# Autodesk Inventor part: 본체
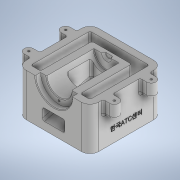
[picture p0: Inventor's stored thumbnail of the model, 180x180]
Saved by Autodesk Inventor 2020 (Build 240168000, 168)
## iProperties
Created: 2022-03
Part Number: 본체
Material: 일반
Document SubType Name: Modeling
Designer: Administrator
Density: 1 g/cm^3
Appearance: 기본값
Mass: 379.403 g
Surface Area: 844.892 cm^2
Volume: 379.403 cm^3
Author: Administrator
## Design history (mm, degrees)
sketch "스케치1"
  geometry: L1 (-55, -55)-(55, -55); L2 (55, -55)-(55, 55); L3 (55, 55)-(-55, 55); L4 (-55, 55)-(-55, -55); L5 (-55, -55)-(55, 55); L6 (55, -55)-(-55, 55); 1 further point
  constraints: 12 end point, 2 midpoint, 2 parallel, 1 horizontal, 1 perpendicular
  dimensions: "d0" = 110 distance of L2.end L3.end; "d1" = 110 distance of L3.end L1.start
extrude "돌출1" new body sketch "스케치1" distance "d2" = 65; taper "d3" = 0 deg
sketch "스케치3"
  geometry: L1 (-45, 45)-(45, 45); L2 (-45, 45)-(-45, -45); L3 (-45, -45)-(-30, -45); L4 (-30, -45)-(-30, 33); L5 (-30, 33)-(30, 33); L6 (30, 33)-(30, -45); L7 (45, 45)-(45, -45); L8 (45, -45)-(30, -45); L9 (-55, 55)-(-55, -55) reference; L10 (55, -55)-(55, 55) reference; L11 (55, 55)-(-55, 55) reference; L12 (-55, -55)-(55, -55) reference; 1 further point
  constraints: 16 end point, 5 perpendicular, 2 vertical, 1 horizontal, 1 point on line
  dimensions: "d5" = 25 distance between parallel lines of L4 L9; "d7" = 25 distance between parallel lines of L6 L10; "d8" = 10 distance between parallel lines of L1 L11; "d9" = 12 distance between parallel lines of L1 L5; "d10" = 15 distance between parallel lines of L4 L2; "d11" = 15 distance between parallel lines of L6 L7; "d12" = 10 distance between parallel lines of L12 L3
extrude "돌출2" cut sketch "스케치3" extent not by distance; stored distance "d13" = 0; taper "d14" = 0 deg
sketch "스케치5"
  geometry: L1 (55, 65)-(-55, 65) reference; L2 (-55, 65)-(55, 65); L3 (-55, 0)-(-55, 65) reference; L4 (-55, 65)-(-55, 37); L5 (-55, 37)-(-47, 37); L6 (-45, 65)-(-45, 0) reference; L7 (-47, 37)-(-47, 46); L8 (-47, 46)-(25, 46); L9 (25, 46)-(25, 65); 2 further points
  constraints: 12 end point, 3 perpendicular, 2 point on line, 1 horizontal, 1 parallel
  dimensions: "d16" = 8 distance of L4.end L5.end; "d17" = 56 diameter of L5 L1; "d18" = 38 diameter of L8 L1; "d19" = 72 distance between parallel lines of L9 L7
revolve "회전1" sketch "스케치5" stored, may be unused: angle "d20" = 90 deg
node "작업 평면1"
fillet "모깎기1" dims "d27" = 13
sketch "스케치7"
  geometry: L1 (-65, 35)-(-47.997, 35); L2 (-47.997, 35)-(-47.997, 21); L3 (-47.997, 21)-(-65, 21); L4 (-45, -45)-(-45, 45) reference; L5 (-55, 42)-(-55, -42) reference; L6 (42, 55)-(-42, 55) reference; A1 r 7 centre (-65, 28) between (-65, 35) and (-65, 21); 3 further points
  constraints: 6 end point, 2 point on circle, 1 centre point, 1 horizontal, 1 perpendicular, 1 tangent, 1 vertical alignment
  dimensions: "d29" = 10 distance from line of A1.centre L5; "d30" = 14 distance between parallel lines of L3 L1; "d31" = 27 distance from line of A1.centre L6
extrude "돌출5" join sketch "스케치7" distance "d32" = 20; taper "d33" = 0 deg
chamfer "모따기1" distance "d34" = 1; stored, may be unused: second distance "d35" = 2, angle "d36" = 45 deg
sketch "스케치8"
  geometry: A1 r 7 centre (-65, 28) between (-65, 35) and (-65, 21) reference; A2 r 7 centre (-65, -28) between (-65, -21) and (-65, -35) reference; A3 r 7 centre (65, -28) between (65, -35) and (65, -21) reference; A4 r 7 centre (65, 28) between (65, 21) and (65, 35) reference; 5 further points
  constraints: 4 coincident
hole "구멍1" sketch "스케치8" at (-65, 28), (-65, -28), (65, -28), (65, 28) diameter "d37" = 3.242; stored, may be unused: countersink angle "d41" = 90 deg, drill point angle "d43" = 118 deg; dims "d38" = 9, "d39" = 4, "d40" = 2, "d42" = 11
fillet "모깎기2" dims "d44" = 3
fillet "모깎기3" dims "d45" = 3
chamfer "모따기2" distance "d46" = 1; stored, may be unused: second distance "d47" = 2, angle "d48" = 45 deg
sketch "스케치10"
  geometry: L1 (-55, 0)-(-55, 65) reference; L2 (-55, 29.197)-(-19, 38.843); L3 (-55, 11.597)-(19, 31.425); L4 (33, 65)-(33, 0) reference; L5 (33, 30)-(-36.449, 11.391); L6 (-36.449, 11.391)-(-36.449, 0); L7 (-45, 0)-(33, 0) reference; L8 (-19, 57.482)-(19, 57.482); L9 (-19, 57.482)-(-19, 38.843); L10 (-18, 65)-(-18, 48) reference; L11 (19, 57.482)-(19, 31.425); L12 (18, 48)-(18, 65) reference; L13 (-55, 29.197)-(-55, 11.597); 1 further point
  constraints: 16 end point, 5 parallel, 4 point on line, 1 horizontal, 1 vertical
  dimensions: "d50" = 17 distance between parallel lines of L3 L2; "d51" = 30 distance from line of L5.start L7; "d52" = 75 deg angle of L4 L5; "d53" = 5 distance between parallel lines of L3 L5; "d54" = 36 distance from line of L8.start L1; "d55" = 38 distance of L8.end L8.start
extrude "돌출6" cut sketch "스케치10" stored distance "d56" = 34; taper "d57" = 0 deg
fillet "모깎기4" dims "d58" = 3
fillet "모깎기5" dims "d59" = 3
sketch "스케치11"
  geometry: L1 (0, 0)-(0, 84) reference; 3 further points
  constraints: 1 horizontal alignment, 1 midpoint, 1 other
  dimensions: "d60" = 20 distance of point (-20, 42) point (0, 42)
feature "엠보싱1" sketch "스케치11" dims "d0" = 110, "d1" = 110, "d12" = 10, "d61" = 0.5, "d62" = 0
sketch "스케치12" dims "d83" = 46
  geometry: L1 (-42, -65)-(42, -65) reference; L2 (-19, 0)-(19, 0) reference; L3 (-6.5, 0)-(6.5, 0) reference; A1 r 6.5 centre (0, 0) between (-6.5, 0) and (6.5, 0) reference; 5 further points
  constraints: 2 vertical alignment, 1 midpoint, 3 other
hole "구멍2" sketch "스케치12" at (0, -23) diameter "d64" = 3.242; stored, may be unused: countersink angle "d68" = 90 deg, drill point angle "d70" = 118 deg; dims "d65" = 9, "d66" = 4, "d67" = 2, "d69" = 11
sketch "스케치14"
  geometry: L1 (33, 65)-(33, 0) reference; L2 (33, 30)-(-45, 9.1); L3 (-55, 11.597)-(16.776, 30.829) reference; L4 (-45, 9.1)-(-45, 0); L5 (-45, 0)-(33, 0) reference; L6 (-42, 0)-(-55, 0) reference; L7 (-55, 0)-(-55, 65) reference; 1 further point
  constraints: 4 end point, 1 parallel, 1 point on line, 1 vertical
  dimensions: "d71" = 5 distance between parallel lines of L3 L2; "d77" = 10 distance between parallel lines of L4 L7
extrude "돌출7" cut sketch "스케치14" stored distance "d72" = 60; taper "d73" = 0 deg
fillet "모깎기7" dims "d75" = 3
fillet "모깎기8" dims "d76" = 3
fillet "모깎기9" dims "d78" = 3
fillet "모깎기10" dims "d82" = 3
fillet "모깎기11" dims "d84" = 3
fillet "모깎기12" dims "d85" = 1
sketch "스케치15"
  geometry: C1 r 7.5 at (0, 0); A1 r 19 centre (0, 0) between (-14, -12.845) and (14, -12.845) reference; 1 further point
  constraints: 1 centre point, 1 coincident
  dimensions: "d86" = 15 diameter of C1
extrude "돌출8" cut sketch "스케치15" distance "d87" = 4; taper "d88" = -30 deg
fillet "모깎기13" dims "d89" = 1
node "솔리드1"
mirror "미러1"
mirror "미러2"
feature "A9D066F2-1C7D-4E18-AEED-F7BC21143FA4" dims "d37" = 3.242, "d38" = 9, "d39" = 4, "d40" = 2, "d41" = 90 deg, "d42" = 11, "d43" = 118 deg
other parameters: "d21" = -4
